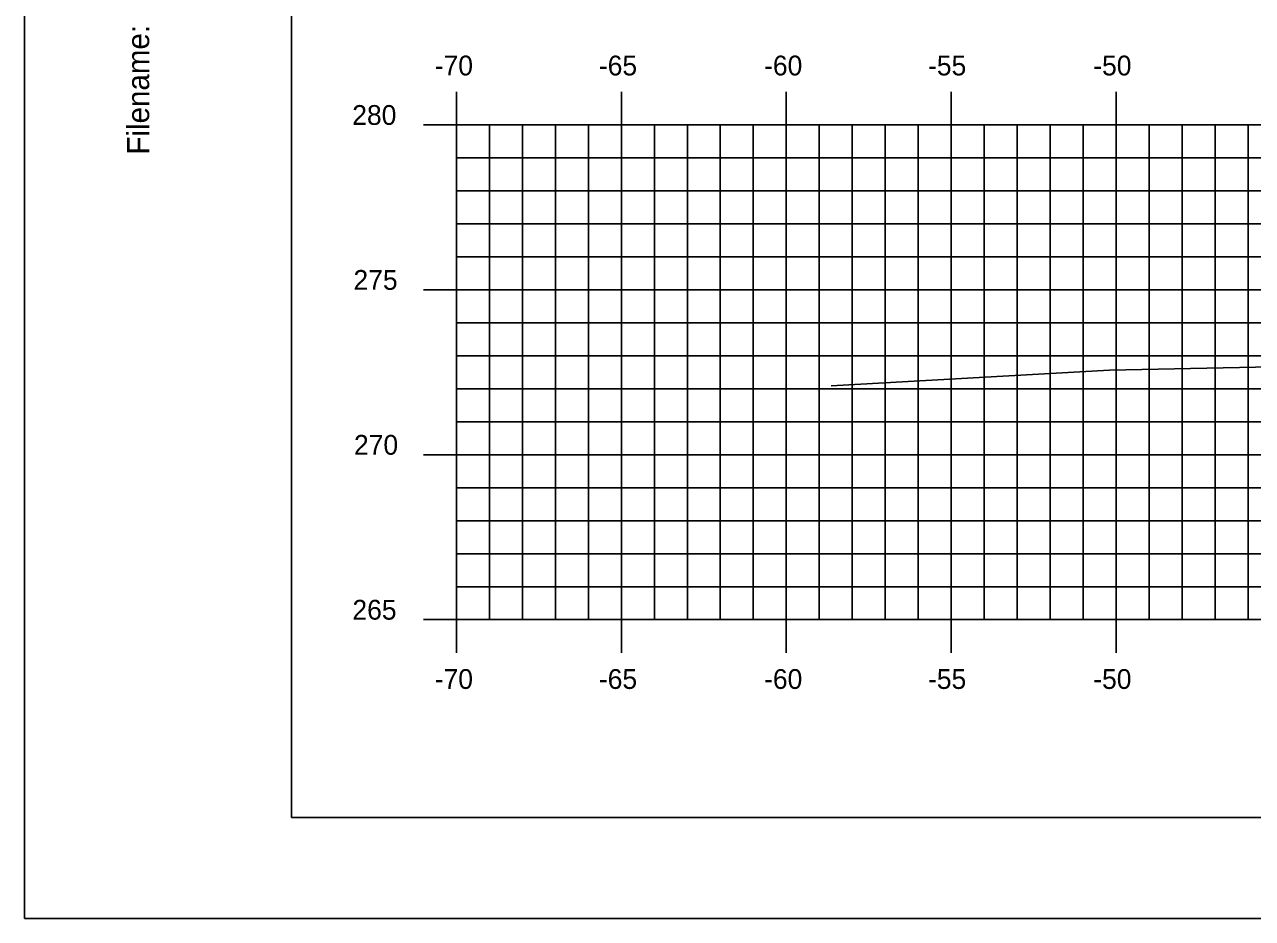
# Model space of a CAD drawing. Extents: x 854676 to 854846, y 366268 to 366378.
# Drawn here: x 854676.01 to 854713.24, y 366268.18 to 366295.28 of the extents above; entities that cross this region are included whole.
import ezdxf

# ---------------------------------------------------------------- set-up
doc = ezdxf.new("R2010")
doc.units = 0
for name, color, linetype in [('BORDER', 7, 'Continuous'), ('H_V ANNOTATION', 7, 'Continuous'), ('MAJOR', 7, 'Continuous'), ('MINOR', 7, 'Continuous'), ('PLOT BOUNDARY', 7, 'Continuous'), ('S_Roadway_Centerline', 7, 'Continuous')]:
    doc.layers.add(name, color=color, linetype=linetype)

msp = doc.modelspace()

# ---------------------------------------------------------------- linework, layer by layer
at = {"layer": 'BORDER'}
for p, q in [((854684.107, 366376.236), (854684.107, 366271.236)), ((854684.107, 366271.236), (854844.107, 366271.236))]:
    msp.add_line(p, q, dxfattribs=at)
at = {"layer": 'MAJOR'}
for p, q in [((854689.106, 366293.238), (854689.106, 366292.236)), ((854694.106, 366293.238), (854694.106, 366292.236)), ((854699.106, 366293.238), (854699.106, 366292.236)), ((854704.106, 366293.238), (854704.106, 366292.236)), ((854709.106, 366293.238), (854709.106, 366292.236)), ((854688.104, 366292.236), (854689.106, 366292.236)), ((854689.106, 366292.236), (854829.106, 366292.236)), ((854689.106, 366277.236), (854689.106, 366292.236)), ((854689.106, 366277.236), (854689.106, 366292.236)), ((854689.106, 366292.236), (854829.106, 366292.236)), ((854694.106, 366277.236), (854694.106, 366292.236)), ((854699.106, 366277.236), (854699.106, 366292.236)), ((854704.106, 366277.236), (854704.106, 366292.236)), ((854709.106, 366277.236), (854709.106, 366292.236)), ((854688.104, 366287.236), (854689.106, 366287.236)), ((854689.106, 366287.236), (854829.106, 366287.236)), ((854688.104, 366282.236), (854689.106, 366282.236)), ((854689.106, 366282.236), (854829.106, 366282.236)), ((854688.104, 366277.236), (854689.106, 366277.236)), ((854689.106, 366277.236), (854829.106, 366277.236)), ((854689.106, 366277.236), (854829.106, 366277.236)), ((854689.106, 366276.234), (854689.106, 366277.236)), ((854694.106, 366276.234), (854694.106, 366277.236)), ((854699.106, 366276.234), (854699.106, 366277.236)), ((854704.106, 366276.234), (854704.106, 366277.236)), ((854709.106, 366276.234), (854709.106, 366277.236))]:
    msp.add_line(p, q, dxfattribs=at)
at = {"layer": 'MINOR'}
for p, q in [((854690.106, 366277.236), (854690.106, 366292.236)), ((854691.106, 366277.236), (854691.106, 366292.236)), ((854692.106, 366277.236), (854692.106, 366292.236)), ((854693.106, 366277.236), (854693.106, 366292.236)), ((854695.106, 366277.236), (854695.106, 366292.236)), ((854696.106, 366277.236), (854696.106, 366292.236)), ((854697.106, 366277.236), (854697.106, 366292.236)), ((854698.106, 366277.236), (854698.106, 366292.236)), ((854700.106, 366277.236), (854700.106, 366292.236)), ((854701.106, 366277.236), (854701.106, 366292.236)), ((854702.106, 366277.236), (854702.106, 366292.236)), ((854703.106, 366277.236), (854703.106, 366292.236)), ((854705.106, 366277.236), (854705.106, 366292.236)), ((854706.106, 366277.236), (854706.106, 366292.236)), ((854707.106, 366277.236), (854707.106, 366292.236)), ((854708.106, 366277.236), (854708.106, 366292.236)), ((854710.106, 366277.236), (854710.106, 366292.236)), ((854711.106, 366277.236), (854711.106, 366292.236)), ((854712.106, 366277.236), (854712.106, 366292.236)), ((854713.106, 366277.236), (854713.106, 366292.236)), ((854689.106, 366291.236), (854829.106, 366291.236)), ((854689.106, 366291.236), (854690.108, 366291.236)), ((854689.106, 366290.236), (854829.106, 366290.236)), ((854689.106, 366290.236), (854690.108, 366290.236)), ((854689.106, 366289.236), (854829.106, 366289.236)), ((854689.106, 366289.236), (854690.108, 366289.236)), ((854689.106, 366288.236), (854829.106, 366288.236)), ((854689.106, 366288.236), (854690.108, 366288.236)), ((854689.106, 366286.236), (854829.106, 366286.236)), ((854689.106, 366286.236), (854690.108, 366286.236)), ((854689.106, 366285.236), (854829.106, 366285.236)), ((854689.106, 366285.236), (854690.108, 366285.236)), ((854689.106, 366284.236), (854829.106, 366284.236)), ((854689.106, 366284.236), (854690.108, 366284.236)), ((854689.106, 366283.236), (854829.106, 366283.236)), ((854689.106, 366283.236), (854690.108, 366283.236)), ((854689.106, 366281.236), (854829.106, 366281.236)), ((854689.106, 366281.236), (854690.108, 366281.236)), ((854689.106, 366280.236), (854829.106, 366280.236)), ((854689.106, 366280.236), (854690.108, 366280.236)), ((854689.106, 366279.236), (854829.106, 366279.236)), ((854689.106, 366279.236), (854690.108, 366279.236)), ((854689.106, 366278.236), (854829.106, 366278.236)), ((854689.106, 366278.236), (854690.108, 366278.236))]:
    msp.add_line(p, q, dxfattribs=at)
at = {"layer": 'PLOT BOUNDARY'}
msp.add_lwpolyline([(854676.013, 366268.177), (854846.013, 366268.177), (854846.013, 366378.177), (854676.013, 366378.177)], close=True, dxfattribs=at)
at = {"layer": 'S_Roadway_Centerline'}
msp.add_lwpolyline([(854700.471, 366284.322), (854708.905, 366284.797), (854721.694, 366285.065), (854732.614, 366285.415), (854735.383, 366285.709), (854736.899, 366285.86), (854739.868, 366285.754), (854740.379, 366285.723), (854740.556, 366285.66), (854741.471, 366285.366), (854747.7, 366285.585), (854748.52, 366285.618), (854758.547, 366285.5), (854759.829, 366285.5), (854761.239, 366285.468), (854771.879, 366285.217)], dxfattribs=at)

# ---------------------------------------------------------------- texts
at = {"layer": 'BORDER'}
msp.add_text('Filename:', height=0.6696, rotation=90, dxfattribs=at).set_placement((854679.791, 366291.335))
at = {"layer": 'H_V ANNOTATION'}
for s, p in [('-70', (854688.448, 366293.736)), ('-65', (854693.424, 366293.736)), ('-60', (854698.432, 366293.736)), ('-55', (854703.402, 366293.736)), ('-50', (854708.411, 366293.736)), ('280', (854685.947, 366292.236)), ('275', (854685.984, 366287.236)), ('270', (854686, 366282.236)), ('265', (854685.952, 366277.236)), ('-70', (854688.448, 366275.136)), ('-65', (854693.424, 366275.136)), ('-60', (854698.432, 366275.136)), ('-55', (854703.402, 366275.136)), ('-50', (854708.411, 366275.136))]:
    msp.add_text(s, height=0.6, dxfattribs=at).set_placement(p)
at = {"layer": 'MAJOR'}
msp.add_text('-', height=0.00000006, rotation=53.1301, dxfattribs=at).set_placement((854689.102, 366277.236))

doc.saveas('drawing.dxf')
